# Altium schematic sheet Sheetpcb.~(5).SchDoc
size A; SheetNumber: 2; SheetTotal: 2
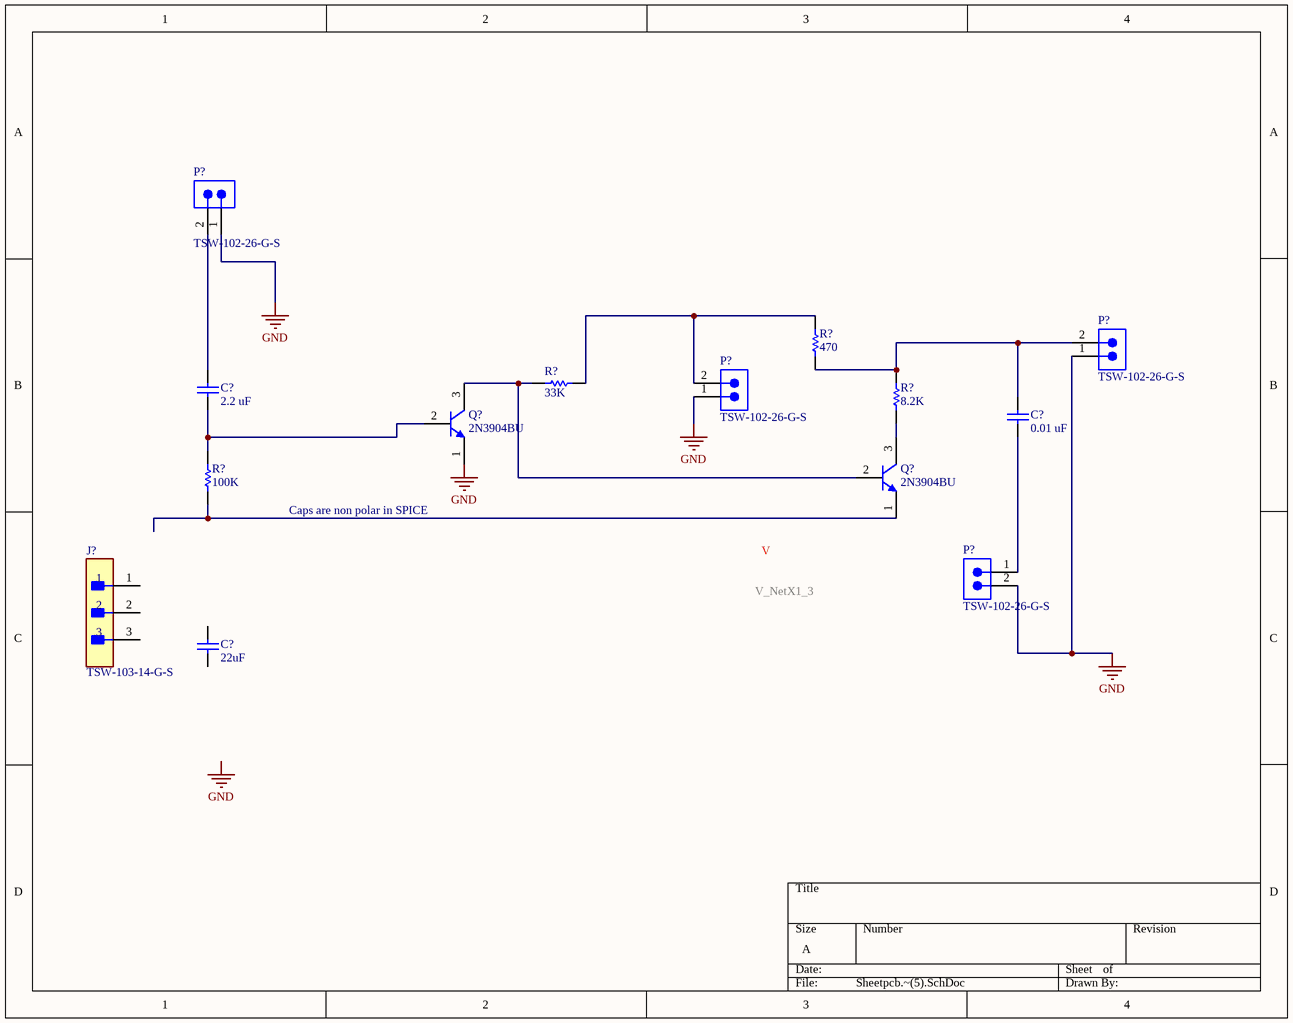
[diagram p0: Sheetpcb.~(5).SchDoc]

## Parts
(Parts that share a designator on the sheet are numbered #1, #2 ... from top to bottom, then left to right.)
C?#1  value 2.2 uF  (hidden comment: Capacitor)
C?#2  value 0.01 uF  (hidden comment: Capacitor)
C?#3  value 22uF  (hidden comment: Capacitor)
J?  TSW-103-14-G-S  [FP-TSW-103-14-G-S-MFG]
P?#1  TSW-102-26-G-S  [SMTC-TSW-102-26-XX-S]
P?#2  TSW-102-26-G-S  [SMTC-TSW-102-26-XX-S]
P?#3  TSW-102-26-G-S  [SMTC-TSW-102-26-XX-S]
P?#4  TSW-102-26-G-S  [SMTC-TSW-102-26-XX-S]
Q?#1  2N3904BU  [FAIR-TO-92]
Q?#2  2N3904BU  [FAIR-TO-92]
R?#1  value 470  (hidden comment: Resistor)
R?#2  value 8.2K  (hidden comment: Resistor)
R?#3  value 33K  (hidden comment: Resistor)
R?#4  value 100K  (hidden comment: Resistor)

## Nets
GND: P?#1.1 P?#2.1 P?#3.1 P?#4.2 Q?#1.1(E)
NetC?#1_1: C?#1.1 Q?#1.2(B) R?#4.2
NetC?#1_2: C?#1.2 P?#1.2
NetC?#2_1: C?#2.1 P?#4.1
NetC?#2_2: C?#2.2 P?#2.2 R?#1.1 R?#2.1
NetP?#3_2: P?#3.2 R?#1.2 R?#3.1
NetQ?#1_3: Q?#1.3(C) Q?#2.2(B) R?#3.2
NetQ?#2_1: Q?#2.1(E) R?#4.1
NetQ?#2_3: Q?#2.3(C) R?#2.2

Not connected (* = marked no-connect by the designer): C?#3 1 2; J? 1 2 3

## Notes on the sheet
- Caps are non polar in SPICE
- Labels drawn without touching a wire or pin: GND

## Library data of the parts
C?#1-C?#3 = Capacitor: SimulationGenericComponent: True
J? = CMP-02766-001743-1: CONN HEADER VERT 3POS 2.54MM; Max Voltage Rating (AC): 550V; Number of Positions: 3; Max Current Rating: 7.6A; Gender: Male
P?#1-P?#4 = CMP-1024-00327-1: 0.025" SQ Post Header, Through-hole, Vertical, -55 to 125 degC, 2.54 mm Pitch, 2-Pin, Male, RoHS; Manufacturer: Samtec; Pitch: 2.54 mm
Q?#1 Q?#2 = CMP-2000-04944-1: NPN General-Purpose Amplifier, 40 V VCEO, 0.2 A, -55 to 150 degC, 2-Pin TO-92, RoHS, Bulk; Manufacturer: FairchildSemiconductor; Maximum Collector Base Voltage: 60V; Minimum DC Current Gain: 40@0.1mA@1V; Maximum Collector Emitter Voltage: 40V; Maximum DC Collector Current: 0.2A; Rad Hard: No; Maximum Operating Frequency: 300(Min)MHz; Maximum Collector Emitter Saturation Voltage: 0.2@1mA@10mA; Maximum Power Dissipation: 625mW
R?#1-R?#4 = Resistor: TC1: 0; SimulationGenericComponent: True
